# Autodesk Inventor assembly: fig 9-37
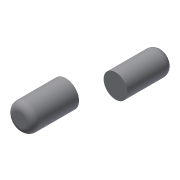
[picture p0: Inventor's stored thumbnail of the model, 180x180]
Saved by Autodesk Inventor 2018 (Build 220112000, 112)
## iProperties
Created: 2013-07
Part Number: fig 9-37
Document SubType Name: Assembly
Designer: CADCIM
Author: CADCIM
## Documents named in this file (3)
- E:\_Deepak\Inventor\Autodesk Inventor_2017_Project\Resources\Inventor_2018_Part\c09_Inv_2018\c09_inv_2018_prt\fig 9-37.iam
- E:\_Deepak\Inventor\Autodesk Inventor_2017_Project\Resources\Inventor_2018_Part\c09_Inv_2018\c09_inv_2018_prt\10.ipt
- E:\_Deepak\Inventor\Autodesk Inventor_2017_Project\Resources\Inventor_2018_Part\c09_Inv_2018\c09_inv_2018_prt\11.ipt
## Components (2 placed, 2 different names)
1. 10:1
2. 11:1
